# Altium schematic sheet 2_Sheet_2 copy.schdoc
size 302 x 215 mm; Name: A_A4; Symbol: A_A4; Device: A_A4; @Project Name: Quectel_EC200U_Board_2024-07-11; REV: 1.1; Date: 11-07-24; Sheet: 1/1; Draw By: Anusha; Company: FervidSmart Solutions; Convert to PCB: yes; Add into BOM: yes
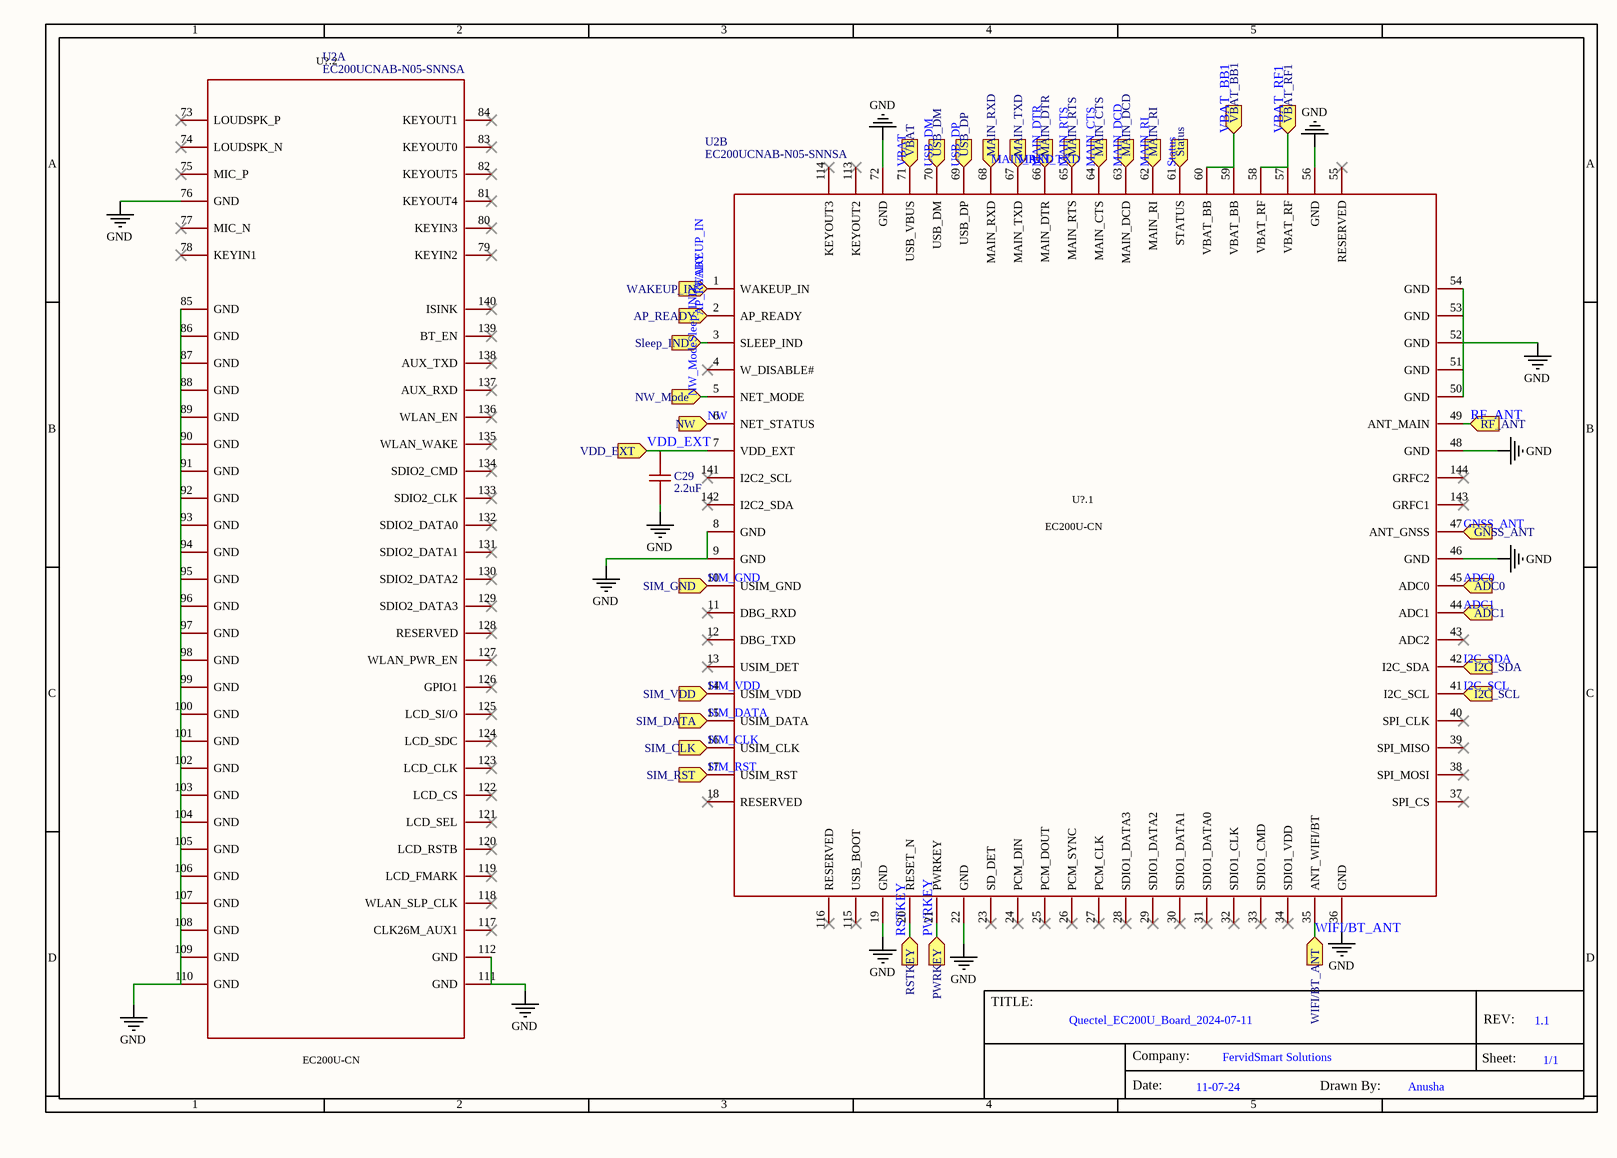
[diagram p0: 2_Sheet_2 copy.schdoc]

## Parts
C29  2.2uF  [C0603]
U2  EC200UCNAB-N05-SNNSA  [LCC-LGA-144_L32.0-W29.0-CAT1-CUIOT-MZ-6]  (parts A,B of 2)

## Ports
ADC0 (in), ADC1 (in), AP_READY (in), GNSS_ANT (in), I2C_SCL (in), I2C_SDA (in), MAIN_CTS (in), MAIN_DCD (in), MAIN_DTR (in), MAIN_RI (in), MAIN_RTS (in), MAIN_RXD (in), MAIN_TXD (in), NW (in), NW_Mode (in), PWRKEY (in), RF_ANT (in), RSTKEY (in), SIM_CLK (in), SIM_DATA (in), SIM_GND (in), SIM_RST (in), SIM_VDD (in), Sleep_IND (in), Status (in), USB_DM (in), USB_DP (in), VBAT (in), VBAT_BB1 (in), VBAT_RF1 (in), VDD_EXT (in), WAKEUP_IN (in), WIFI/BT_ANT (in)

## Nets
GND: C29.1 U2.8(GND) U2.9(GND) U2.19(GND) U2.22(GND) U2.36(GND) U2.46(GND) U2.48(GND) U2.50(GND) U2.51(GND) U2.52(GND) U2.53(GND) U2.54(GND) U2.56(GND) U2.72(GND) U2.76(GND) U2.85(GND) U2.86(GND) U2.87(GND) U2.88(GND) U2.89(GND) U2.90(GND) U2.91(GND) U2.92(GND) U2.93(GND) U2.94(GND) U2.95(GND) U2.96(GND) U2.97(GND) U2.98(GND) U2.99(GND) U2.100(GND) U2.101(GND) U2.102(GND) U2.103(GND) U2.104(GND) U2.105(GND) U2.106(GND) U2.107(GND) U2.108(GND) U2.109(GND) U2.110(GND) U2.111(GND) U2.112(GND)
ADC0: U2.45(ADC0) ; port ADC0
ADC1: U2.44(ADC1) ; port ADC1
AP_READY: U2.2(AP_READY) ; port AP_READY
GNSS_ANT: U2.47(ANT_GNSS) ; port GNSS_ANT
I2C_SCL: U2.41(I2C_SCL) ; port I2C_SCL
I2C_SDA: U2.42(I2C_SDA) ; port I2C_SDA
MAIN_CTS: U2.64(MAIN_CTS) ; port MAIN_CTS
MAIN_DCD: U2.63(MAIN_DCD) ; port MAIN_DCD
MAIN_DTR: U2.66(MAIN_DTR) ; port MAIN_DTR
MAIN_RI: U2.62(MAIN_RI) ; port MAIN_RI
MAIN_RTS: U2.65(MAIN_RTS) ; port MAIN_RTS
MAIN_RXD: U2.68(MAIN_RXD) ; port MAIN_RXD
MAIN_TXD: U2.67(MAIN_TXD) ; port MAIN_TXD
NW: U2.6(NET_STATUS) ; port NW
NW_Mode: U2.5(NET_MODE) ; port NW_Mode
PWRKEY: U2.21(PWRKEY) ; port PWRKEY
RF_ANT: U2.49(ANT_MAIN) ; port RF_ANT
RSTKEY: U2.20(RESET_N) ; port RSTKEY
SIM_CLK: U2.16(USIM_CLK) ; port SIM_CLK
SIM_DATA: U2.15(USIM_DATA) ; port SIM_DATA
SIM_GND: U2.10(USIM_GND) ; port SIM_GND
SIM_RST: U2.17(USIM_RST) ; port SIM_RST
SIM_VDD: U2.14(USIM_VDD) ; port SIM_VDD
Sleep_IND: U2.3(SLEEP_IND) ; port Sleep_IND
Status: U2.61(STATUS) ; port Status
USB_DM: U2.70(USB_DM) ; port USB_DM
USB_DP: U2.69(USB_DP) ; port USB_DP
VBAT: U2.71(USB_VBUS) ; port VBAT
VBAT_BB1: U2.59(VBAT_BB) U2.60(VBAT_BB) ; port VBAT_BB1
VBAT_RF1: U2.57(VBAT_RF) U2.58(VBAT_RF) ; port VBAT_RF1
VDD_EXT: C29.2 U2.7(VDD_EXT) ; port VDD_EXT
WAKEUP_IN: U2.1(WAKEUP_IN) ; port WAKEUP_IN
WIFI/BT_ANT: U2.35(ANT_WIFI/BT) ; port WIFI/BT_ANT

Not connected (* = marked no-connect by the designer): U2 4(W_DISABLE#)* 11(DBG_RXD)* 12(DBG_TXD)* 13(USIM_DET)* 18(RESERVED)* 23(SD_DET)* 24(PCM_DIN)* 25(PCM_DOUT)* 26(PCM_SYNC)* 27(PCM_CLK)* 28(SDIO1_DATA3)* 29(SDIO1_DATA2)* 30(SDIO1_DATA1)* 31(SDIO1_DATA0)* 32(SDIO1_CLK)* 33(SDIO1_CMD)* 34(SDIO1_VDD)* 37(SPI_CS)* 38(SPI_MOSI)* 39(SPI_MISO)* 40(SPI_CLK)* 43(ADC2)* 55(RESERVED)* 73(LOUDSPK_P)* 74(LOUDSPK_N)* 75(MIC_P)* 77(MIC_N)* 78(KEYIN1)* 79(KEYIN2)* 80(KEYIN3)* 81(KEYOUT4)* 82(KEYOUT5)* 83(KEYOUT0)* 84(KEYOUT1)* 113(KEYOUT2)* 114(KEYOUT3)* 115(USB_BOOT)* 116(RESERVED)* 117(CLK26M_AUX1)* 118(WLAN_SLP_CLK)* 119(LCD_FMARK)* 120(LCD_RSTB)* 121(LCD_SEL)* 122(LCD_CS)* 123(LCD_CLK)* 124(LCD_SDC)* 125(LCD_SI/O)* 126(GPIO1)* 127(WLAN_PWR_EN)* 128(RESERVED)* 129(SDIO2_DATA3)* 130(SDIO2_DATA2)* 131(SDIO2_DATA1)* 132(SDIO2_DATA0)* 133(SDIO2_CLK)* 134(SDIO2_CMD)* 135(WLAN_WAKE)* 136(WLAN_EN)* 137(AUX_RXD)* 138(AUX_TXD)* 139(BT_EN)* 140(ISINK)* 141(I2C2_SCL)* 142(I2C2_SDA)* 143(GRFC1)* 144(GRFC2)*

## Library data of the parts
C29 = 0603X225K160CT: Manufacturer: Walsin Tech Corp; Convert to PCB: yes
U2 = EC200UCNAB-N05-SNNSA: Manufacturer: 移远 Quectel; Convert to PCB: yes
